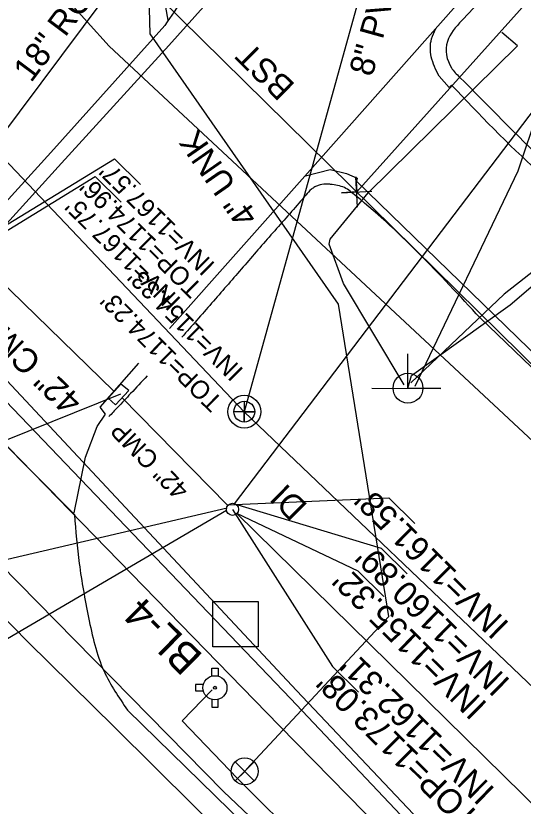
# Model space of a CAD drawing. Extents: x 1263837 to 1268319, y 770628 to 773628.
# Drawn here: x 1267130.7 to 1267214, y 771843 to 771972.7 of the extents above; entities that cross this region are included whole.
import ezdxf

# ---------------------------------------------------------------- set-up
doc = ezdxf.new("R2010")
doc.units = 0
for name, color, linetype in [('CTL Secondary Horizontal and Vertical Text', 7, 'Continuous'), ('Exist Roads EOP Other', 7, 'Continuous'), ('Exist Roads EOT Text', 7, 'Continuous'), ('Exist Structure Minor Catch Basin Top Elevation', 7, 'Continuous'), ('Exist Structure Minor Drop Inlet', 7, 'Continuous'), ('Exist Structure Minor Drop Inlet Leader', 7, 'Continuous'), ('Exist Structure Minor Drop Inlet Text', 7, 'Continuous'), ('Exist Structure Minor Drop Inlet Top Elevation', 7, 'Continuous'), ('Exist Utilities Gas UG Line SUE LOS B', 7, 'Continuous'), ('Exist Utilities Power Joint Use Telephone CELL', 7, 'Continuous'), ('Exist Utilities Power UG Cable SUE LOS B', 7, 'Continuous'), ('Exist Utilities Telephone UG Cable SUE LOS B', 7, 'Continuous'), ('Exist Utilities Telephone UG FO SUE LOS B', 7, 'Continuous'), ('Exist Utilities TV UG Cable SUE LOS B', 7, 'Continuous'), ('Exist Utilities Water Fire Hydrant CELL', 7, 'Continuous'), ('Exist Utilities Water UG Line SUE LOS B', 7, 'Continuous'), ('Exist Utilities Water UG Line SUE LOS B Text', 7, 'Continuous'), ('Exist Utilities Water Valve CELL', 7, 'Continuous'), ('Prop CMT Slope Fill', 7, 'Continuous'), ('Prop Drainage Structure Drop Inlet Grate 2 Narrow Slots and Sag Grates 840 24 CELL', 7, 'Continuous'), ('Prop Drainage Structure Drop Inlet Grate 2 Narrow Slots and Sag Grates 840 24 Label', 7, 'Continuous'), ('Prop Drainage Structure Junction Box with Manhole Convert From Catch Basin CELL', 7, 'Continuous'), ('Prop Drainage Structure Junction Box with Slab Lid CELL', 7, 'Continuous'), ('Prop Drainage Structure Pipe RCP 18in Class III Label', 7, 'Continuous'), ('Prop Drainage Structure Pipe RCP 42in Class III', 7, 'Continuous'), ('Prop Drainage Structure Pipe RCP 60in Class III', 7, 'Continuous'), ('Prop Drainage Structure Pipe Welded Steel 60in', 7, 'Continuous'), ('Prop Drainage Structure Plot Symbol 20 Scale CELL', 7, 'Continuous'), ('Prop Drainage Structure Plot Symbol 50 Scale CELL', 7, 'Continuous'), ('Prop Drainage Structure Tops and Inverts LABEL', 7, 'Continuous'), ('Prop Erosion Rip Rap Class B', 7, 'Continuous'), ('Prop Erosion Rip Rap Single Stone CELL', 7, 'Continuous'), ('Prop Guardrail', 7, 'Continuous'), ('Prop Horizontal Alignment', 7, 'Continuous'), ('Prop Retaining Wall', 7, 'Continuous'), ('Prop Shade Heavy', 7, 'Continuous'), ('Prop SS Fill Line', 7, 'Continuous'), ('Prop SS Fill Text', 7, 'Continuous'), ('Prop SS Transition Line', 7, 'Continuous'), ('Prop WCR CELL', 7, 'Continuous'), ('Scratch_Level_0', 7, 'Continuous'), ('Scratch_Level_5', 7, 'Continuous')]:
    doc.layers.add(name, color=color, linetype=linetype)

# ---------------------------------------------------------------- blocks, each defined once
blk = doc.blocks.new('EXIST UTILITIES SANITARY SEWER MANHOLE')
at = {"layer": 'Prop WCR CELL'}
blk.add_lwpolyline([(0, 0.03425), (0, -0.03425), (0, 0), (0.03425, 0), (-0.03425, 0)], dxfattribs=at)
for radius in [0.05389, 0.03425]:
    blk.add_circle((0, 0), radius, dxfattribs=at)
blk = doc.blocks.new('CTL SECONDARY HORIZONTAL AND VERTICAL')
at = {"layer": 'Prop CMT Slope Fill'}
blk.add_line((0, 0), (0, 0), dxfattribs=at)
blk.add_lwpolyline([(-0.1043, 0.0004), (0.0005, 0.1052), (0.1055, 0.0002), (0.0007, -0.1047)], close=True, dxfattribs=at)
blk = doc.blocks.new('EXIST UTILITIES POWER JOINT USE TELEPHONE')
at = {"layer": 'Exist Utilities Power Joint Use Telephone CELL'}
blk.add_line((0, 0), (0, 0), dxfattribs=at)
blk.add_lwpolyline([(-0.1188, 0), (0.108, -0.0008), (0, -0.0004), (0, 0.1125)], dxfattribs=at)
blk.add_circle((0, 0.0001), 0.049, dxfattribs=at)
blk = doc.blocks.new('EXIST UTILITIES WATER VALVE')
at = {"layer": 'Exist Utilities Water Valve CELL'}
blk.add_lwpolyline([(0.0315, 0.0315), (-0.0315, -0.0315), (0, 0), (0.0315, -0.0315), (-0.0315, 0.0315)], dxfattribs=at)
blk.add_circle((0, 0), 0.0445, dxfattribs=at)
blk = doc.blocks.new('EXIST UTILITIES WATER FIRE HYDRANT')
at = {"layer": 'Exist Utilities Water Fire Hydrant CELL'}
blk.add_line((0, 0), (0, 0), dxfattribs=at)
for points in [[(-0.01025, 0.03825), (-0.01025, 0.064), (0.01025, 0.064), (0.01025, 0.03775)], [(-0.03825, 0.01025), (-0.064, 0.01025), (-0.064, -0.01025), (-0.03825, -0.01025)], [(-0.01025, -0.03825), (-0.01025, -0.064), (0.01025, -0.064), (0.01025, -0.03775)]]:
    blk.add_lwpolyline(points, dxfattribs=at)
for radius in [0.03954, 0.00485]:
    blk.add_circle((0, 0), radius, dxfattribs=at)

msp = doc.modelspace()

# ---------------------------------------------------------------- linework, layer by layer
at = {"layer": 'Exist Roads EOP Other'}
msp.add_lwpolyline([(1267155.77, 771971.93), (1267154.55, 771978.76), (1267131.51, 772001.83), (1267111.96, 772024.71), (1267102.24, 772036.12), (1267078.14, 772061.16), (1267050.03, 772089.91), (1267027.35, 772112.96), (1267015.53, 772125.08)], dxfattribs=at)
at = {"layer": 'Exist Structure Minor Drop Inlet'}
msp.add_lwpolyline([(1267149.3, 771911.15), (1267148, 771912.22), (1267145.91, 771909.9), (1267147.13, 771908.85), (1267149.3, 771911.15)], dxfattribs=at)
msp.add_circle((1267166.32, 771891.67), 1, dxfattribs=at)
at = {"layer": 'Exist Structure Minor Drop Inlet Leader'}
for points in [[(1267122.84, 771934.47), (1267146.94, 771949.19), (1267151.22, 771944.98)], [(1267147.95, 771910.56), (1267129.05, 771902.97), (1267124.78, 771907.18)]]:
    msp.add_lwpolyline(points, dxfattribs=at)
at = {"layer": 'Exist Utilities Gas UG Line SUE LOS B'}
msp.add_lwpolyline([(1267251.66, 771778.25), (1267245.66, 771783.24), (1267207.76, 771821.81), (1267173.99, 771856.22), (1267107.23, 771924.68), (1267058.55, 771976.3), (1267021.45, 772013.9), (1266984.81, 772050.66), (1266941.85, 772095.07), (1266910.9, 772129.48), (1266882, 772160.62)], dxfattribs=at)
at = {"layer": 'Exist Utilities Power UG Cable SUE LOS B'}
for points in [[(1267194.51, 771912.1), (1267184.57, 771928.72), (1267182.18, 771935.2), (1267182.38, 771936), (1267188.6, 771943.62), (1267213.12, 771967.76), (1267210.52, 771969.92)], [(1267262.66, 771969.81), (1267250.05, 771956.54), (1267242.19, 771950.19), (1267238.47, 771948.54), (1267210.93, 771927), (1267195.58, 771912.43)]]:
    msp.add_lwpolyline(points, dxfattribs=at)
at = {"layer": 'Exist Utilities Telephone UG Cable SUE LOS B'}
for points in [[(1267392.03, 771642.05), (1267309.91, 771722.47), (1267265.68, 771767.66), (1267210.14, 771824.35), (1267175.87, 771860.6), (1267111.82, 771927.45), (1267061.85, 771976.15)], [(1267195.13, 771911.54), (1267195.73, 771913.64), (1267211.9, 771925.25), (1267249.07, 771957.03), (1267261.66, 771970.8)], [(1267198.93, 771813.02), (1267164.82, 771845.39), (1267091.52, 771919.94)]]:
    msp.add_lwpolyline(points, dxfattribs=at)
at = {"layer": 'Exist Utilities Telephone UG FO SUE LOS B'}
for points in [[(1267402.3, 771719.43), (1267352.82, 771769), (1267334.68, 771788.64), (1267283.58, 771836.93), (1267255.34, 771868.58), (1267217.3, 771901.29), (1267146.08, 771967.68), (1267135.38, 771979.55), (1267117.02, 771999.86), (1267114.01, 772002.75), (1267108.97, 771998.49)], [(1268035.78, 770997.15), (1267940.84, 771107.94), (1267897.35, 771156.24), (1267867.85, 771183.87), (1267810.07, 771229.4), (1267770.21, 771268.8), (1267721.65, 771316.15), (1267671.88, 771358.99), (1267623.8, 771405.23), (1267607.14, 771420.63), (1267574.79, 771453.25), (1267517.7, 771508.8), (1267479.52, 771551.33), (1267465.41, 771567.06), (1267416.72, 771620.51), (1267391.64, 771647.4), (1267311.09, 771724.38), (1267266.64, 771768.8), (1267249.06, 771785.93), (1267211.37, 771825.47), (1267176.84, 771861.92), (1267114.4, 771928.7), (1267064.3, 771976.43)]]:
    msp.add_lwpolyline(points, dxfattribs=at)
at = {"layer": 'Exist Utilities TV UG Cable SUE LOS B'}
msp.add_lwpolyline([(1267196.29, 771911.87), (1267213.2, 771947.25), (1267216.57, 771957.19), (1267275.52, 771957.13)], dxfattribs=at)
at = {"layer": 'Exist Utilities Water UG Line SUE LOS B'}
for p, q in [((1267124.08, 771933.2), (1267146.77, 771911.1)), ((1267148.16, 771910.02), (1267165.47, 771892.41))]:
    msp.add_line(p, q, dxfattribs=at)
for points in [[(1267168.62, 771849.04), (1267191.96, 771874.07), (1267183.71, 771925.32), (1267152.83, 771969.69), (1267152.66, 771975.95)], [(1267460.35, 771562.06), (1267407.65, 771611.49), (1267384.09, 771634.71), (1267349.53, 771669.13), (1267303.81, 771713.68), (1267255.61, 771762.88), (1267237.59, 771778.93), (1267200.46, 771814.35), (1267167.14, 771847.51), (1267158.06, 771856.95), (1267162.99, 771862.03)]]:
    msp.add_lwpolyline(points, dxfattribs=at)
at = {"layer": 'Prop Drainage Structure Drop Inlet Grate 2 Narrow Slots and Sag Grates 840 24 Label'}
for points in [[(1267123.56, 771933.92), (1267143.78, 771946.27), (1267148.05, 771942.06)], [(1267165.47, 771892.41), (1267192, 771893.54), (1267196.27, 771889.33)]]:
    msp.add_lwpolyline(points, dxfattribs=at)
at = {"layer": 'Prop Drainage Structure Junction Box with Slab Lid CELL'}
msp.add_lwpolyline([(1267166.65, 771892.55), (1267190.75, 771885.29), (1267195.02, 771881.08)], dxfattribs=at)
at = {"layer": 'Prop Drainage Structure Pipe RCP 18in Class III Label'}
for p, q in [((1267165.43, 771891.84), (1266953.49, 771842.57)), ((1267167, 771891.05), (1267312.91, 771747.5))]:
    msp.add_line(p, q, dxfattribs=at)
at = {"layer": 'Prop Drainage Structure Pipe RCP 42in Class III'}
msp.add_line((1267165.35, 771891.46), (1267096.96, 771851.53), dxfattribs=at)
at = {"layer": 'Prop Drainage Structure Pipe RCP 60in Class III'}
msp.add_line((1267186.71, 771943.76), (1267186.71, 771943.76), dxfattribs=at)
msp.add_lwpolyline([(1267186.84, 771941.26), (1267186.57, 771946.26), (1267186.71, 771943.76), (1267184.21, 771943.62), (1267189.2, 771943.9)], dxfattribs=at)
at = {"layer": 'Prop Drainage Structure Plot Symbol 50 Scale CELL'}
msp.add_lwpolyline([(1267166.32, 771891.67), (1267182.75, 771865.87), (1267187.02, 771861.66)], dxfattribs=at)
at = {"layer": 'Prop Erosion Rip Rap Single Stone CELL'}
msp.add_lwpolyline([(1267167, 771891.05), (1267186.88, 771881.59), (1267191.16, 771877.38)], dxfattribs=at)
at = {"layer": 'Prop Guardrail'}
msp.add_line((1267322.98, 772095.82), (1267186.71, 771943.76), dxfattribs=at)
at = {"layer": 'Prop Horizontal Alignment'}
msp.add_line((1268113.05, 771031.32), (1267144.12, 771985.71), dxfattribs=at)
at = {"layer": 'Prop Shade Heavy'}
msp.add_line((1267158.35, 771993.02), (1267117.4, 771938.33), dxfattribs=at)
at = {"layer": 'Prop SS Fill Line'}
for points in [[(1267155.19, 771971.1), (1267136.49, 771950.23), (1267123.6, 771936.07), (1267121.36, 771933.85), (1267120.53, 771932.95), (1267119.45, 771931.66)], [(1267343.08, 771791.32), (1267315.33, 771818.66), (1267295.07, 771838.44), (1267264.81, 771867.47), (1267240.77, 771890.68), (1267206.97, 771923.09)]]:
    msp.add_lwpolyline(points, dxfattribs=at)
for points in [[(1267239.41, 772011.38), (1267203.98, 771971.9), (1267201.59, 771968.44), (1267202.25, 771964.15), (1267203.61, 771962.6), (1267218.02, 771948.28), (1267222.08, 771945.7), (1267225.9, 771946.6), (1267229.99, 771949.79), (1267230.8, 771950.74), (1267241.64, 771963.29), (1267243.88, 771966.96), (1267243.92, 771971.19), (1267242.44, 771973.7), (1267238.42, 771976.83), (1267234.51, 771978.89), (1267227.98, 771982.62)], [(1267159.05, 771991.06), (1267160.06, 771984.89), (1267159.53, 771979.48), (1267158.11, 771975.68), (1267155.19, 771971.1)], [(1267206.97, 771923.09), (1267185.87, 771943.69), (1267184.95, 771944.34), (1267183.86, 771944.76), (1267182.7, 771944.98), (1267182.13, 771945.02), (1267181.59, 771945.03), (1267180.4, 771944.83), (1267179.82, 771944.58), (1267179.29, 771944.2), (1267178.36, 771943.25), (1267177.53, 771942.28), (1267172.63, 771936.71), (1267167.77, 771931.1), (1267162.9, 771925.5), (1267158.01, 771919.92)], [(1267152.31, 771913.59), (1267149.6, 771910.67), (1267147.43, 771908.38), (1267146.03, 771906.89)]]:
    msp.add_spline(points, degree=3, dxfattribs=at)
at = {"layer": 'Prop SS Fill Text'}
msp.add_line((1267122.12, 771909.18), (1267140.36, 771890.81), dxfattribs=at)
for points in [[(1267213.05, 772032.03), (1267189.78, 772005.9), (1267176.3, 771990.61), (1267155.85, 771967.82), (1267138.24, 771948.5), (1267125.42, 771934.43), (1267121.06, 771929.94), (1267119.7, 771931.05), (1267117.27, 771928.82), (1267108.72, 771923.59)], [(1267156, 771921.34), (1267178.17, 771946.34), (1267208.16, 771980.23), (1267237.37, 772012.66)], [(1267202.3, 771961.31), (1267201.91, 771960.92), (1267200.24, 771962.76)], [(1267178.28, 771946.38), (1267182.33, 771947.46), (1267185.05, 771946.8), (1267186.77, 771946.05), (1267186.68, 771945.55), (1267216.91, 771916.21), (1267242.27, 771891.97), (1267266.18, 771869.06), (1267296.62, 771839.86), (1267316.76, 771820.04), (1267320.69, 771817.08), (1267345.07, 771792.93)], [(1267140.31, 771891.08), (1267142.18, 771900.24), (1267144.13, 771905.29), (1267145.47, 771907.28), (1267144.58, 771908.46), (1267150.95, 771915.65)], [(1267149.09, 771858.72), (1267175.45, 771832.94), (1267207.22, 771802.01), (1267236.14, 771773.57), (1267263.9, 771746.15), (1267277.64, 771732.87)]]:
    msp.add_lwpolyline(points, dxfattribs=at)
for points in [[(1267230.45, 771983.51), (1267239.53, 771978.43), (1267244.6, 771974.92), (1267246.01, 771971.92), (1267246.08, 771966.42), (1267243.37, 771961.89), (1267232.26, 771949.26), (1267226.69, 771944.7), (1267222.13, 771943.75), (1267216.74, 771946.94), (1267202.3, 771961.31)], [(1267200.24, 771962.76), (1267198.96, 771965.96), (1267199, 771968.89), (1267199.68, 771970.51)], [(1267140.36, 771890.81), (1267141.16, 771882.79), (1267142.69, 771873.92), (1267145.23, 771865.1), (1267149.09, 771858.72)]]:
    msp.add_spline(points, degree=3, dxfattribs=at)
at = {"layer": 'Prop SS Transition Line'}
msp.add_lwpolyline([(1266892.05, 772132.4), (1266918.74, 772103.45), (1266946.95, 772072.12), (1266975.02, 772041.09), (1267002.55, 772011.32), (1267028.69, 771982.73), (1267054.25, 771954.75), (1267080.46, 771925.43), (1267105.81, 771897.39), (1267132.71, 771869.91), (1267147, 771855.87), (1267172.96, 771830.15)], dxfattribs=at)
at = {"layer": 'Scratch_Level_0'}
msp.add_line((1267166.65, 771892.55), (1267321.36, 772096.24), dxfattribs=at)
at = {"layer": 'Scratch_Level_5'}
for p, q in [((1267168.26, 771907.7), (1267056.62, 772025.19)), ((1267191.27, 771990.75), (1267168.26, 771907.7)), ((1267168.26, 771907.7), (1267283.38, 771797.71))]:
    msp.add_line(p, q, dxfattribs=at)

# ---------------------------------------------------------------- block references
at = {"layer": 'Exist Utilities Power Joint Use Telephone CELL', "xscale": 50, "yscale": 50}
msp.add_blockref('EXIST UTILITIES POWER JOINT USE TELEPHONE', (1267195.13, 771911.56), dxfattribs=at)
at = {"layer": 'Exist Utilities Water Fire Hydrant CELL', "xscale": 50, "yscale": 50}
msp.add_blockref('EXIST UTILITIES WATER FIRE HYDRANT', (1267163.44, 771862.39), dxfattribs=at)
at = {"layer": 'Exist Utilities Water Valve CELL', "xscale": 50, "yscale": 50}
msp.add_blockref('EXIST UTILITIES WATER VALVE', (1267168.32, 771848.67), dxfattribs=at)
at = {"layer": 'Prop CMT Slope Fill', "xscale": 50, "yscale": 49.99999999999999, "rotation": 44.99999999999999}
msp.add_blockref('CTL SECONDARY HORIZONTAL AND VERTICAL', (1267166.81, 771872.79), dxfattribs=at)
msp.add_blockref('CTL SECONDARY HORIZONTAL AND VERTICAL', (1267166.81, 771872.79), dxfattribs=at)
at = {"layer": 'Prop WCR CELL', "xscale": 50, "yscale": 50}
msp.add_blockref('EXIST UTILITIES SANITARY SEWER MANHOLE', (1267168.26, 771907.7), dxfattribs=at)

# ---------------------------------------------------------------- texts
at = {"layer": 'CTL Secondary Horizontal and Vertical Text'}
msp.add_text('BL-4', height=5, rotation=135.4333, dxfattribs=at).set_placement((1267161.65, 771867.66))
at = {"layer": 'Exist Roads EOT Text'}
msp.add_text('BST', height=4, rotation=135.4333, dxfattribs=at).set_placement((1267176.76, 771961.32))
at = {"layer": 'Exist Structure Minor Catch Basin Top Elevation'}
msp.add_text("TOP=1173.08'", height=4, rotation=135.4333, dxfattribs=at).set_placement((1267207.17, 771841.46))
at = {"layer": 'Exist Structure Minor Drop Inlet Text'}
msp.add_text('DI', height=4, rotation=135.4333, dxfattribs=at).set_placement((1267178.81, 771892.35))
at = {"layer": 'Exist Structure Minor Drop Inlet Top Elevation'}
msp.add_text("TOP=1174.96'", height=3, rotation=135.4333, dxfattribs=at).set_placement((1267161.54, 771928.28))
at = {"layer": 'Exist Utilities Water UG Line SUE LOS B Text'}
msp.add_text('4" UNK ', height=4, rotation=124.8354, dxfattribs=at).set_placement((1267170.68, 771939.78))
at = {"layer": 'Prop Drainage Structure Drop Inlet Grate 2 Narrow Slots and Sag Grates 840 24 CELL'}
for s, height, p in [("INV=1167.57'", 3, (1267163.61, 771931.91)), ("INV=1167.75'", 3, (1267158.01, 771926.14)), ("INV=1161.58'", 4, (1267211.93, 771872.9))]:
    msp.add_text(s, height=height, rotation=135.4333, dxfattribs=at).set_placement(p)
at = {"layer": 'Prop Drainage Structure Junction Box with Manhole Convert From Catch Basin CELL'}
msp.add_text("INV=1160.89'", height=4, rotation=135.4333, dxfattribs=at).set_placement((1267212.09, 771863.52))
at = {"layer": 'Prop Drainage Structure Pipe Welded Steel 60in'}
for height, rotation, p in [(4, 135.7577, (1267141.85, 771909.64)), (3, 134.5195, (1267159.34, 771895.03))]:
    msp.add_text('42" CMP', height=height, rotation=rotation, dxfattribs=at).set_placement(p)
at = {"layer": 'Prop Drainage Structure Plot Symbol 20 Scale CELL'}
msp.add_text("INV=1162.31'", height=4, rotation=135.4333, dxfattribs=at).set_placement((1267209.58, 771845.7))
at = {"layer": 'Prop Drainage Structure Tops and Inverts LABEL'}
msp.add_text('18" RCP', height=4, rotation=53.1766, dxfattribs=at).set_placement((1267133.26, 771961.57))
at = {"layer": 'Prop Erosion Rip Rap Class B'}
msp.add_text("INV=1155.32'", height=4, rotation=135.4333, dxfattribs=at).set_placement((1267208.32, 771859.69))
at = {"layer": 'Prop Retaining Wall'}
for s, p in [("INV=1154.33'", (1267168.27, 771914.57)), ("TOP=1174.23'", (1267164.9, 771909.58))]:
    msp.add_text(s, height=3, rotation=135.4333, dxfattribs=at).set_placement(p)
at = {"layer": 'Scratch_Level_0'}
msp.add_text('8" PVC', height=4, rotation=74.5166, dxfattribs=at).set_placement((1267189.26, 771962.54))

doc.saveas('drawing.dxf')
